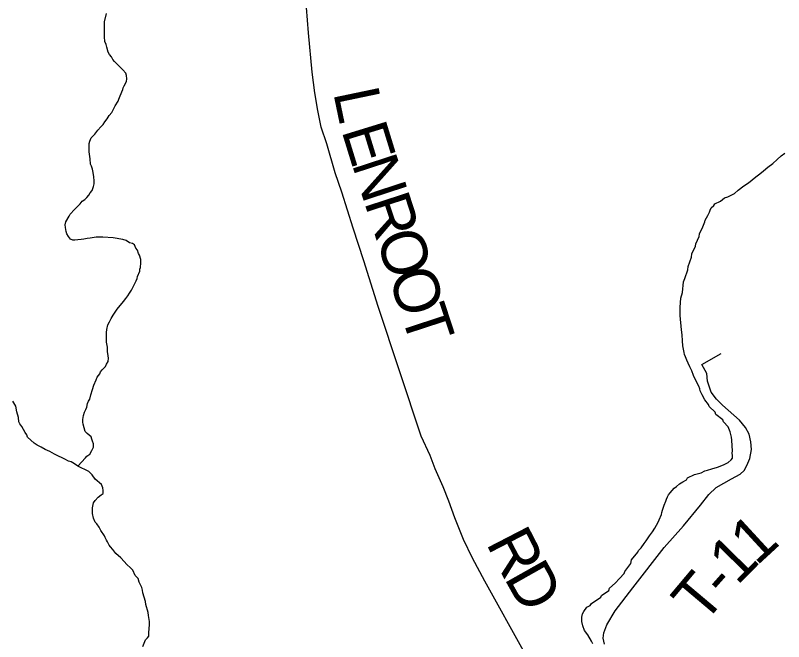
# Model space of a CAD drawing. Extents: x 1310247 to 1664935, y 235267 to 584339.
# Drawn here: x 1521003 to 1526070, y 315364 to 319493 of the extents above; entities that cross this region are included whole.
import ezdxf

# ---------------------------------------------------------------- set-up
doc = ezdxf.new("R2010")
doc.units = 0
for name, color, linetype in [('GM_X_County_Road', 7, 'Continuous'), ('GM_X_County_Road_Text', 7, 'Continuous'), ('GM_X_Minor_River', 7, 'Continuous'), ('GM_X_Township_Road', 7, 'Continuous'), ('GM_X_Township_Road_Text', 7, 'Continuous')]:
    doc.layers.add(name, color=color, linetype=linetype)

msp = doc.modelspace()

# ---------------------------------------------------------------- linework, layer by layer
at = {"layer": 'GM_X_County_Road'}
msp.add_lwpolyline([(1524365.3, 315283.7), (1524099.6, 315762.3), (1524019, 315914.2), (1523957.8, 316036.5), (1523902.1, 316181.4), (1523861.8, 316289.9), (1523823.9, 316385.1), (1523772.7, 316504.4), (1523737.9, 316591.2), (1523679.8, 316718.2), (1523396.3, 317572.6), (1523300.2, 317875.4), (1523231.3, 318090), (1523156.9, 318327), (1523112.8, 318454.1), (1523057, 318645.4), (1523019, 318755.4), (1522997.3, 318865.3), (1522978, 318983.1), (1522960.2, 319119.4), (1522935.4, 319377.3), (1522916, 319631.4)], dxfattribs=at)
at = {"layer": 'GM_X_Minor_River'}
for points in [[(1521513.7, 318350.8), (1521517.9, 318364.8), (1521522.1, 318382.9), (1521522.3, 318403), (1521520.6, 318429.1), (1521517, 318457.3), (1521511.2, 318479.4), (1521505.4, 318499.6), (1521499.5, 318511.7), (1521495.9, 318547.9), (1521490.4, 318592.2), (1521488.7, 318614.3), (1521489.1, 318648.5), (1521493.3, 318662.5), (1521503.6, 318686.5), (1521526, 318710.3), (1521546.4, 318736.1), (1521566.7, 318758), (1521580.9, 318773.9), (1521593.2, 318791.8), (1521607.5, 318809.7), (1521621.8, 318831.6), (1521638.1, 318853.5), (1521650.4, 318873.5), (1521660.7, 318895.4), (1521681.2, 318927.3), (1521685.3, 318941.3), (1521693.6, 318963.3), (1521712.2, 319003.2), (1521714.3, 319015.3), (1521720.5, 319029.3), (1521734.9, 319057.2), (1521737.1, 319075.3), (1521735.4, 319097.4), (1521731.5, 319111.5), (1521711.7, 319133.8), (1521683.9, 319162.3), (1521656.1, 319188.8), (1521646.2, 319201), (1521636.4, 319219.2), (1521624.6, 319235.4), (1521614.7, 319249.6), (1521607.1, 319283.8), (1521601.2, 319300), (1521593.4, 319320.1), (1521591.8, 319352.3), (1521590.7, 319426.7), (1521590.9, 319450.8), (1521603.6, 319504.8)], [(1525886.3, 318428.2), (1525912.6, 318447.9), (1525937, 318467.7), (1525965.4, 318491.5), (1525997.8, 318517.2), (1526028.2, 318542.9), (1526054.6, 318566.7), (1526076.9, 318584.5)], [(1525108, 315953), (1525112.2, 315965), (1525130.5, 315982.9), (1525150.9, 316010.7), (1525163.1, 316028.7), (1525185.6, 316062.5), (1525206, 316088.4), (1525220.4, 316112.3), (1525232.6, 316132.2), (1525245, 316156.2), (1525249.1, 316168.2), (1525265.6, 316202.1), (1525267.8, 316216.2), (1525272, 316230.2), (1525282.4, 316264.2), (1525292.7, 316290.2), (1525296.9, 316304.2), (1525303.1, 316318.2), (1525311.3, 316332.1), (1525321.5, 316346.1), (1525335.7, 316360), (1525348, 316375.9), (1525364.2, 316387.7), (1525382.4, 316403.6), (1525404.7, 316417.3), (1525429, 316431.1), (1525437.1, 316443), (1525481.6, 316466.6), (1525525.9, 316476.1), (1525550.1, 316489.8), (1525568.3, 316493.6), (1525596.5, 316503.3), (1525632.8, 316514.9), (1525673.1, 316530.5), (1525691.3, 316538.3), (1525703.4, 316544.2), (1525723.7, 316562), (1525731.9, 316573.9), (1525732, 316588), (1525730.3, 316608.1), (1525732.4, 316620.1), (1525729.3, 316692.5), (1525725.5, 316712.6), (1525717.8, 316746.9), (1525714, 316759), (1525704.2, 316779.2), (1525674.5, 316813.7), (1525668.6, 316825.8), (1525622.8, 316862.6), (1525619, 316876.7), (1525579.2, 316913.3), (1525575.4, 316927.5), (1525549.6, 316957.9), (1525532, 316990.3), (1525520.2, 317016.5), (1525518.4, 317030.6), (1525510.6, 317048.8), (1525488.9, 317089.2), (1525475.2, 317119.5), (1525463.6, 317149.8), (1525451.8, 317176.1), (1525440.1, 317200.3), (1525432.3, 317220.5), (1525422.5, 317240.8), (1525416.6, 317256.9), (1525414.8, 317271), (1525405.2, 317313.3), (1525403.6, 317347.5), (1525400.1, 317387.7), (1525396.5, 317419.9), (1525387.5, 317514.4), (1525388.2, 317568.6), (1525392.9, 317628.8), (1525403.4, 317664.9), (1525410.2, 317735.1), (1525418.5, 317757.1), (1525439.3, 317815.1), (1525441.5, 317837.1), (1525462.4, 317899.2), (1525464.6, 317921.2), (1525489.3, 317971.1), (1525491.5, 317987.2), (1525512.2, 318035.1), (1525514.4, 318053.2), (1525537, 318099.1), (1525551.4, 318131.1), (1525553.6, 318143.1), (1525570, 318173), (1525580.3, 318195), (1525584.5, 318209), (1525592.7, 318223), (1525608.9, 318238.8), (1525617.1, 318250.8), (1525653.5, 318268.4), (1525679.8, 318290.2), (1525702, 318295.9), (1525746.4, 318317.5), (1525770.8, 318341.2), (1525807.3, 318368.9), (1525837.6, 318388.6), (1525886.3, 318428.2)], [(1521415.8, 316521.9), (1521464.6, 316575.5), (1521474.8, 316587.5), (1521493, 316599.3), (1521507.3, 316623.2), (1521517.7, 316647.2), (1521517.9, 316667.3), (1521512.1, 316685.4), (1521508.2, 316699.5), (1521502.4, 316713.7), (1521476.5, 316736.1), (1521462.7, 316750.3), (1521449.1, 316796.7), (1521447.3, 316810.8), (1521447.5, 316828.9), (1521449.7, 316840.9), (1521451.8, 316855), (1521458.1, 316877), (1521468.4, 316894.9), (1521474.6, 316908.9), (1521478.9, 316933), (1521485.1, 316949), (1521493.3, 316962.9), (1521499.6, 316991), (1521512.1, 317027), (1521520.5, 317055), (1521535, 317091), (1521543.2, 317106.9), (1521559.5, 317128.8), (1521563.7, 317142.8), (1521575.9, 317156.7), (1521598.2, 317178.5), (1521604.4, 317192.5), (1521614.7, 317210.5), (1521617, 317232.6), (1521615.1, 317248.6), (1521613.3, 317262.8), (1521611.4, 317274.8), (1521609.8, 317305), (1521604.2, 317339.2), (1521604.9, 317401.5), (1521607.1, 317421.5), (1521613.5, 317451.6), (1521623.8, 317471.5), (1521634.1, 317493.5), (1521648.4, 317515.4), (1521660.7, 317535.4), (1521675, 317555.3), (1521715.8, 317607), (1521732.1, 317626.9), (1521744.3, 317642.8), (1521756.6, 317660.7), (1521768.8, 317680.7), (1521789.4, 317720.6), (1521799.7, 317742.5), (1521805.9, 317758.5), (1521808.1, 317770.6), (1521824.6, 317806.5), (1521824.7, 317818.6), (1521828.9, 317830.6), (1521831.2, 317860.7), (1521829.5, 317882.8), (1521821.8, 317911), (1521815.9, 317923.1), (1521808.1, 317945.3), (1521798.2, 317957.5), (1521788.4, 317979.7), (1521776.5, 317987.9), (1521756.5, 317994.2), (1521734.6, 318008.5), (1521712.5, 318014.8), (1521648.4, 318025.7), (1521580.2, 318030.6), (1521536, 318031.1), (1521521.9, 318029.3), (1521495.8, 318023.6), (1521475.7, 318021.8), (1521455.5, 318018.1), (1521437.4, 318014.3), (1521415.3, 318012.6), (1521395.2, 318010.8), (1521381.2, 318011), (1521367.2, 318017.2), (1521353.3, 318035.4), (1521341.5, 318051.7), (1521337.6, 318067.8), (1521333.9, 318093.9), (1521332.1, 318112), (1521336.4, 318132.1), (1521356.9, 318170), (1521365.1, 318182), (1521393.6, 318213.7), (1521420, 318239.5), (1521430.2, 318251.4), (1521442.4, 318267.3), (1521460.6, 318279.2), (1521474.9, 318293.1), (1521487.1, 318307), (1521497.3, 318322.9), (1521509.5, 318338.8), (1521513.7, 318350.8)], [(1521067, 316743.3), (1521045.3, 316781.7), (1521031.5, 316800), (1521025.6, 316814.1), (1521024, 316842.2), (1521012.3, 316878.5), (1521006.8, 316916.8), (1520985.1, 316949.2)], [(1521843.5, 315331.3), (1521860.1, 315375.3), (1521874.3, 315389.1), (1521882.5, 315401.1), (1521882.7, 315423.2), (1521887.4, 315477.4), (1521887.6, 315497.5), (1521880.1, 315535.7), (1521878.3, 315555.8), (1521862.8, 315608.3), (1521861.1, 315628.4), (1521843.7, 315684.8), (1521841.9, 315703), (1521836.1, 315721.1), (1521820.4, 315755.5), (1521812.7, 315779.6), (1521792.8, 315800), (1521777.2, 315834.3), (1521759.3, 315852.6), (1521739.4, 315871), (1521697.8, 315915.7), (1521666, 315944.2), (1521646.2, 315970.6), (1521630.4, 315988.9), (1521622.5, 316001), (1521610.7, 316021.3), (1521604.8, 316033.4), (1521594.9, 316049.6), (1521591.1, 316061.7), (1521567.4, 316096.1), (1521555.6, 316118.4), (1521539.8, 316140.7), (1521529.9, 316152.8), (1521518.2, 316179.1), (1521512.5, 316209.3), (1521512.6, 316221.4), (1521510.9, 316245.5), (1521513.1, 316257.5), (1521519.3, 316279.5), (1521529.6, 316295.5), (1521547.9, 316317.4), (1521568.1, 316331.2), (1521582.3, 316341), (1521582.6, 316361.1), (1521580.7, 316377.2), (1521571, 316399.4), (1521529.2, 316436.1), (1521509.5, 316464.5), (1521487.6, 316484.9), (1521415.8, 316521.9), (1521393.9, 316536.2), (1521371.9, 316548.6), (1521353.9, 316554.8), (1521330, 316567.2), (1521312, 316575.5), (1521288, 316587.8), (1521260.1, 316600.2), (1521230.1, 316616.7), (1521200.2, 316631.1), (1521172.2, 316645.5), (1521146.3, 316659.9), (1521126.4, 316672.2), (1521082.7, 316712.9), (1521078.8, 316727), (1521067, 316743.3)], [(1524811.7, 315350.1), (1524801.9, 315366.3), (1524778.3, 315408.8), (1524756.5, 315437.2), (1524744.9, 315467.4), (1524739.2, 315497.6), (1524739.5, 315525.8), (1524743.8, 315547.8), (1524752, 315561.8), (1524772.4, 315591.6), (1524794.7, 315603.4), (1524802.8, 315615.4), (1524863.6, 315656.8), (1524869.7, 315668.8), (1524916.3, 315702.3), (1524920.5, 315716.3), (1524959, 315750), (1524987.5, 315779.8), (1525018, 315813.5), (1525022.2, 315825.5), (1525063, 315879.3), (1525067.3, 315903.3), (1525108, 315953)]]:
    msp.add_lwpolyline(points, dxfattribs=at)
at = {"layer": 'GM_X_Township_Road'}
msp.add_lwpolyline([(1524887.7, 315348.3), (1524879.7, 315386.9), (1524884.8, 315422.1), (1524903.3, 315474.6), (1524958.1, 315566.3), (1525074.6, 315718), (1525282.8, 315985.4), (1525409.7, 316127.5), (1525522.7, 316264.8), (1525576.9, 316333.9), (1525626, 316379.5), (1525726.9, 316438.3), (1525784, 316467.8), (1525809.5, 316493.3), (1525828.4, 316524.3), (1525846.9, 316572.1), (1525859, 316629.8), (1525854.4, 316682.3), (1525841.7, 316730.8), (1525819.2, 316776.3), (1525779.4, 316824.8), (1525666.9, 316923.4), (1525627.7, 316962.6), (1525592.5, 317008.7), (1525568.9, 317080.8), (1525562.5, 317132.2), (1525529.7, 317191), (1525658.9, 317264.3)], dxfattribs=at)

# ---------------------------------------------------------------- texts
at = {"layer": 'GM_X_County_Road_Text'}
for s, rotation, p in [('L', 281.7915, (1523098.8, 318984.2)), ('E', 287.1043, (1523152.2, 318735.1)), ('N', 288.0855, (1523219.9, 318515.3)), ('R', 288.0872, (1523301.8, 318264.4)), ('O', 288.0885, (1523378.4, 318030.1)), ('O', 288.0915, (1523460.3, 317779.2)), ('T', 288.0926, (1523542.3, 317528.2)), ('R', 297.313, (1524104.1, 316014.6)), ('D', 299.4025, (1524222.8, 315785.3))]:
    msp.add_text(s, height=300, rotation=rotation, dxfattribs=at).set_placement(p)
at = {"layer": 'GM_X_Township_Road_Text'}
for s, rotation, p in [('1', 42.6278, (1525890.3, 315858.7)), ('1', 45.5501, (1525763.8, 315729.6)), ('T', 49.9198, (1525541.5, 315470.3)), ('-', 48.3801, (1525684.6, 315640.4))]:
    msp.add_text(s, height=300, rotation=rotation, dxfattribs=at).set_placement(p)

doc.saveas('drawing.dxf')
